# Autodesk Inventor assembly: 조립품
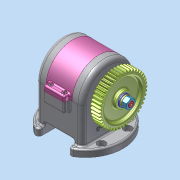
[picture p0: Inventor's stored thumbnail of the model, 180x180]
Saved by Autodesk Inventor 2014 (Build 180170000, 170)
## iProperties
Created: 2024-08
Part Number: 조립품
Document SubType Name: Assembly
Designer: dg
Author: dg
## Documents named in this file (21)
- C:\Users\dg\Desktop\740804V1017\조립품.iam
- C:\Users\dg\Desktop\740804V1017\본체.ipt
- C:\Users\dg\Documents\Inventor\깊은 홈 볼 베어링 6904.ipt
- C:\Users\dg\Desktop\740804V1017\가져온 구성요소\부시 커버\부시 커버.ipt
- C:\Users\dg\Desktop\740804V1017\가져온 구성요소\칼라\칼라.ipt
- C:\Users\dg\Desktop\740804V1017\가져온 구성요소\편심축\편심축.ipt
- C:\Users\dg\Desktop\740804V1017\가져온 구성요소\뒷커버\뒷커버.ipt
- C:\Users\dg\Desktop\740804V1017\가져온 구성요소\앞커버\앞커버.ipt
- C:\Users\dg\Desktop\740804V1017\가져온 구성요소\오일실 20 32 5\오일실 20 32 5.ipt
- C:\Users\dg\Desktop\740804V1017\가져온 구성요소\육각 소켓 머리 볼트 M4x10\육각 소켓 머리 볼트 M4x10.ipt
- C:\Users\dg\Desktop\740804V1017\가져온 구성요소\평행키 5x5x12\평행키 5x5x12.ipt
- C:\Users\dg\Desktop\740804V1017\가져온 구성요소\스퍼 기어\스퍼 기어.ipt
- C:\Users\dg\Desktop\740804V1017\가져온 구성요소\평와셔 M10\평와셔 M10.ipt
- C:\Users\dg\Desktop\740804V1017\가져온 구성요소\스프링 와셔 M10\스프링 와셔 M10.ipt
- C:\Users\dg\Desktop\740804V1017\가져온 구성요소\육각 너트 M10x1\육각 너트 M10x1.ipt
- C:\Users\dg\Desktop\740804V1017\가져온 구성요소\링크\링크.ipt
- C:\Users\dg\Desktop\740804V1017\가져온 구성요소\펀치\펀치.ipt
- C:\Users\dg\Desktop\740804V1017\가져온 구성요소\핀\핀.ipt
- C:\Users\dg\Desktop\740804V1017\가져온 구성요소\E형 멈춤링 10-8\E형 멈춤링 10-8.ipt
- C:\Users\dg\Desktop\740804V1017\가져온 구성요소\오일레스 부시 20 15\오일레스 부시 20 15.ipt
- C:\Users\dg\Desktop\740804V1017\가져온 구성요소\윗커버\윗커버.ipt
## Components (2 placed, 2 different names)
1. 핀:1
2. E형 멈춤링 10-8:1
